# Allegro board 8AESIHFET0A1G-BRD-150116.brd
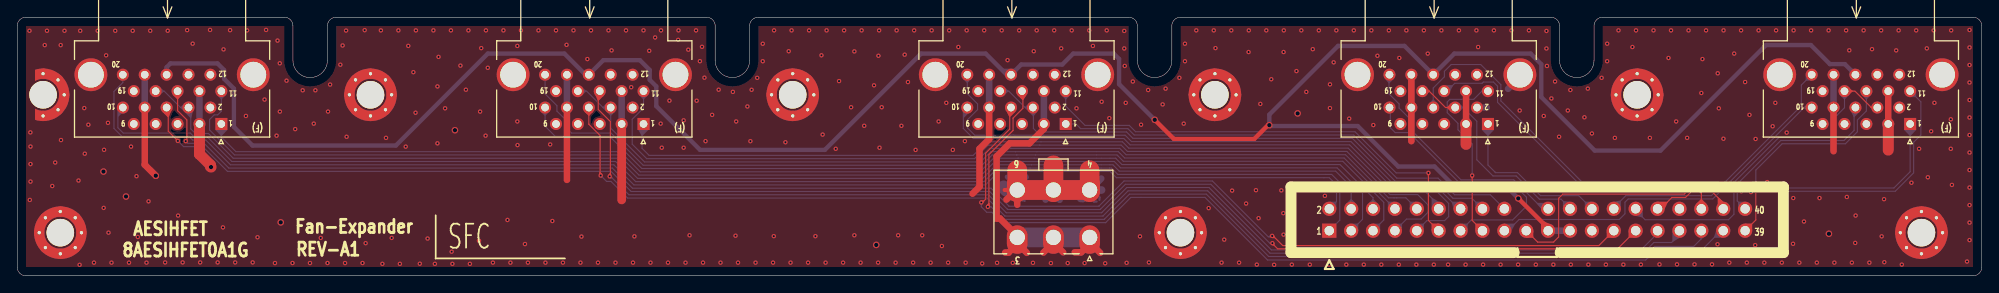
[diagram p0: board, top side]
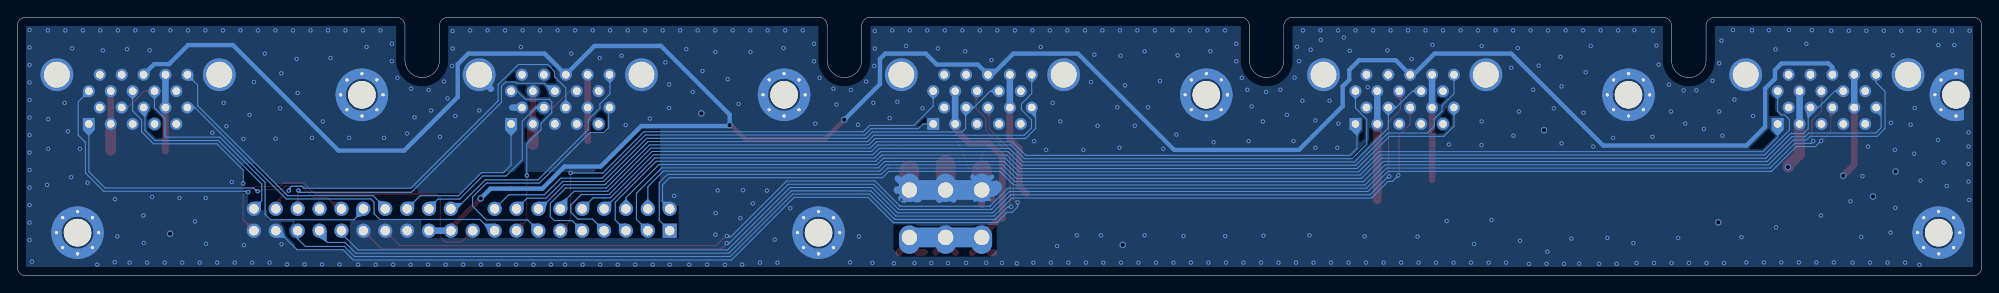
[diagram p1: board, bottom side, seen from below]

Outline 228 x 30 mm; copper layers: TOP, BOTTOM. Coordinates in mm from the lower left corner of the outline.
Outline path: 0,29 0,1 arc(0.29,0.29) 1,0 227,0 arc(227.71,0.29) 228,1 228,29 arc(227.71,29.71) 227,30 184,30 arc(183.29,29.71) 183,29 183,25 arc(181,23) 179,25 179,29 arc(178.71,29.71) 178,30 135,30 arc(134.29,29.71) 134,29 134,25 arc(132,23) 130,25 130,29 arc(129.71,29.71) 129,30 86,30 arc(85.29,29.71) 85,29 85,25 arc(83,23) 81,25 81,29 arc(80.71,29.71) 80,30 37,30 arc(36.29,29.71) 36,29 36,25 arc(34,23) 32,25 32,29 arc(31.71,29.71) 31,30 1,30 arc(0.29,29.71) 0,29

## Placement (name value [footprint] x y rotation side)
A1  3.5mm_8via  [A126_3_NO_ETCH]  3 21 180 top
A2  3.5mm_8via  [A126_DG]  41 21 0 top
A3  3.5mm_8via  [A126_DG]  90 21 0 top
A4  3.5mm_8via  [A126_DG]  139 21 0 top
A5  3.5mm_8via  [A126_DG]  188 21 0 top
A6  3.5mm_8via  [A126_DG]  5 5 0 top
A7  3.5mm_8via  [A126_DG]  135 5 0 top
A8  3.5mm_8via  [A126_DG]  221 5 0 top
JP1  JS-1150-06-A  [P2052_2X3]  124.46 4.45 180 top
JP2  M2554-2X10-G3  [P2X20_HD]  152.27 5.23 0 top
NOREF  -  []  2.54 76.45 0 top
NOREF#2  -  []  29.97 -13.08 0 top
NOREF#3  -  []  48.56 2.01 0 top
NOREF#4  -  []  0 0 0 top
NOREF#5  -  []  24.13 6.73 180 bottom
P1  SM401V-20P  [CHAMP050_20F]  8.55 23.33 180 top
P2  SM401V-20P  [CHAMP050_20F]  57.55 23.33 180 top
P3  SM401V-20P  [CHAMP050_20F]  106.55 23.33 180 top
P4  SM401V-20P  [CHAMP050_20F]  155.55 23.33 180 top
P5  SM401V-20P  [CHAMP050_20F]  204.55 23.33 180 top

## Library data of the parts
A1 = SCREW HOLE_0: Tolerance: ***; User Part Number: ***; room: SCREW
A2-A8 = SCREW HOLE_6: Tolerance: ***; User Part Number: ***; room: SCREW
JP1 = JS_1150_06_A: Tolerance: ***; User Part Number: ***
JP2 = HEADER_20X2_1: Tolerance: ***; User Part Number: ***
P1-P5 = CHAMP050_0: Tolerance: ***; User Part Number: ***

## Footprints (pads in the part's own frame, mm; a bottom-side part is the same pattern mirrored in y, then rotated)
A126_3_NO_ETCH
  round 3.2 hole 3.2 unplated: (0,0)
  round 1.194 hole 0.381: 3(-1.732,1.732) 4(-1.732,-1.732) 6(0,2.451) 7(0,-2.451) 8(-2.451,0)
A126_DG
  round 3.2 hole 3.2 unplated: (0,0)
  round 1.194 hole 0.381: 2(1.732,1.732) 3(-1.732,1.732) 4(-1.732,-1.732) 5(1.732,-1.732) 6(0,2.451) 7(0,-2.451) 8(-2.451,0) 9(2.451,0)
CHAMP050_20F
  rect 1.397x1.397 hole 0.889: 1(-15.138,5.715)
  round 1.397 hole 0.889: 2(-13.868,3.81) 3(-12.598,5.715) 4(-11.328,3.81) 5(-10.058,5.715) 6(-8.788,3.81) 7(-7.518,5.715) 8(-6.248,3.81) 9(-4.978,5.715) 10(-3.708,3.81) 11(-15.138,1.905) 12(-13.868,0) 13(-12.598,1.905) 14(-11.328,0) 15(-10.058,1.905) 16(-8.788,0) 17(-7.518,1.905) 18(-6.248,0) 19(-4.978,1.905) 20(-3.708,0)
  round 3.81 hole 2.997: 21(-18.847,0) 22(0,0)
P2X20_HD
  rect 1.651x1.651 hole 1.092: 1(0,0)
  round 1.651 hole 1.092: 2(0,2.54) 3(2.54,0) 4(2.54,2.54) 5(5.08,0) 6(5.08,2.54) 7(7.62,0) 8(7.62,2.54) 9(10.16,0) 10(10.16,2.54) 11(12.7,0) 12(12.7,2.54) 13(15.24,0) 14(15.24,2.54) 15(17.78,0) 16(17.78,2.54) 17(20.32,0) 18(20.32,2.54) 19(22.86,0) 21(25.4,0) 22(25.4,2.54) 23(27.94,0) 24(27.94,2.54) 25(30.48,0) 26(30.48,2.54) 27(33.02,0) 28(33.02,2.54) 29(35.56,0) 30(35.56,2.54) 31(38.1,0) 32(38.1,2.54) 33(40.64,0) 34(40.64,2.54) 35(43.18,0) 36(43.18,2.54) 37(45.72,0) 38(45.72,2.54) 39(48.26,0) 40(48.26,2.54)
P2052_2X3
  oval 2.413x3.302 hole 1.778: 1(0,0) 2(4.2,0) 3(8.4,0) 4(0,-5.5) 5(4.2,-5.5) 6(8.4,-5.5)

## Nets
12VIN: JP1.1 JP1.2 JP1.3 P1.3 P1.8 P1.13 P1.18 P2.3 P2.8 P2.13 P2.18 P3.3 P3.8 P3.13 P3.18 P4.3 P4.8 P4.13 P4.18 P5.3 P5.8 P5.13 P5.18
GND: A1.3 A1.4 A1.6 A1.7 A1.8 A2.2 A2.3 A2.4 A2.5 A2.6 A2.7 A2.8 A2.9 A3.2 A3.3 A3.4 A3.5 A3.6 A3.7 A3.8 A3.9 A4.2 A4.3 A4.4 A4.5 A4.6 A4.7 A4.8 A4.9 A5.2 A5.3 A5.4 A5.5 A5.6 A5.7 A5.8 A5.9 A6.2 A6.3 A6.4 A6.5 A6.6 A6.7 A6.8 A6.9 A7.2 A7.3 A7.4 A7.5 A7.6 A7.7 A7.8 A7.9 A8.2 A8.3 A8.4 A8.5 A8.6 A8.7 A8.8 A8.9 JP1.4 JP1.5 JP1.6 JP2.25 JP2.34 P1.2 P1.7 P1.9 P1.12 P1.14 P1.19 P1.21 P1.22 P2.2 P2.7 P2.9 P2.12 P2.14 P2.19 P2.21 P2.22 P3.2 P3.7 P3.9 P3.12 P3.14 P3.19 P3.21 P3.22 P4.2 P4.7 P4.9 P4.12 P4.14 P4.19 P4.21 P4.22 P5.2 P5.7 P5.9 P5.12 P5.14 P5.19 P5.21 P5.22
BIAS3V3_VCC: JP2.21 JP2.23 P1.16 P2.16 P3.16 P4.16 P5.16
FAN_DIRECTION_0: JP2.3 P1.11
FAN_DIRECTION_1: JP2.7 P2.11
FAN_DIRECTION_2: JP2.11 P3.11
FAN_DIRECTION_3: JP2.15 P4.11
FAN_DIRECTION_4: JP2.19 P5.11
FAN_PRESENT_0: JP2.1 P1.10
FAN_PRESENT_1: JP2.5 P2.10
FAN_PRESENT_2: JP2.9 P3.10
FAN_PRESENT_3: JP2.13 P4.10
FAN_PRESENT_4: JP2.17 P5.10
FAN_PWM_0: JP2.4 P1.4 P1.17
FAN_PWM_1: JP2.10 P2.4 P2.17
FAN_PWM_2: JP2.16 P3.4 P3.17
FAN_PWM_3: JP2.24 P4.4 P4.17
FAN_PWM_4: JP2.30 P5.4 P5.17
FAN_TACH_0: JP2.6 P1.1
FAN_TACH_1: JP2.2 P1.20
FAN_TACH_2: JP2.12 P2.1
FAN_TACH_3: JP2.8 P2.20
FAN_TACH_4: JP2.18 P3.1
FAN_TACH_5: JP2.14 P3.20
FAN_TACH_6: JP2.26 P4.1
FAN_TACH_7: JP2.22 P4.20
FAN_TACH_8: JP2.32 P5.1
FAN_TACH_9: JP2.28 P5.20
I2C_SCL_FAN0: JP2.29 P1.6
I2C_SCL_FAN1: JP2.33 P2.6
I2C_SCL_FAN2: JP2.37 P3.6
I2C_SCL_FAN3: JP2.38 P4.6
I2C_SCL_FAN4: JP2.40 P5.6
I2C_SDA_FAN0: JP2.27 P1.15
I2C_SDA_FAN1: JP2.31 P2.15
I2C_SDA_FAN2: JP2.35 P3.15
I2C_SDA_FAN3: JP2.36 P4.15
I2C_SDA_FAN4: JP2.39 P5.15

Pads without a net: P1 5; P2 5; P3 5; P4 5; P5 5

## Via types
v1: diameter 0.508, hole 0.254, TOP to BOTTOM, 463 vias
v2: diameter 0.762, hole 0.508, TOP to BOTTOM, 12 vias

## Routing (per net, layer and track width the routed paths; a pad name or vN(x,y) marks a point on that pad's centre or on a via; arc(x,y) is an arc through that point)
12VIN: length 133.5
  TOP w0.762: P5.3 P5.13 ; 121.39,2.72 120.26,3.84 120.26,3.85 ; 120.26,3.85 119.1,2.69 ; 120.26,3.85 JP1.2 ; 124.46,3.89 JP1.1 ; 124.46,3.89 125.68,2.67 ; 124.46,3.89 124.46,3.71 123.47,2.72 122.73,2.72 ; P1.8 14.8,12.89 v2(16.08,11.61) ; P4.3 P4.13 ; P3.8 112.8,15.85 111.68,14.73 111.68,10.34 110.87,9.53 ; 116.06,3.78 JP1.3 116.06,4.64 114.06,6.64 113.67,6.64 113.67,13.84 115.19,15.37 117.47,15.37 119.15,17.04 P3.3 ; 116.06,3.78 116.06,3.69 115.06,2.69 114.66,2.69 ; 116.06,3.78 117.17,2.67 ; 161.8,15.62 P4.8 P4.18 ; P2.8 63.8,11.13 ; P5.8 210.8,14.46
  TOP w1.016: P2.3 70.15,8.81
  TOP w1.27: P1.3 21.15,14.11 21.16,14.11 22.43,12.84 22.43,12.67 v2(22.49,12.61) ; P4.3 168.15,15.24 ; P5.3 217.15,14.58
  BOTTOM w0.762: P3.3 P3.13 ; P2.13 P2.3 ; P3.8 P3.18 ; P1.3 P1.13 ; P2.8 P2.18 ; P5.8 P5.18 ; P1.8 P1.18
  BOTTOM w2.286: JP1.1 JP1.2 JP1.3
GND: length 51.4
  TOP w0.508: 115.92,9.95 114.61,9.95
  TOP w0.762: 114.81,8.84 115.92,9.95 JP1.6 116.06,8.25
  TOP w2.286: JP1.5 JP1.4 124.46,12.24 ; JP1.5 120.26,12.81 ; JP1.5 JP1.6 116.06,12.26
  BOTTOM w0.254: 125.6,8.81 125.6,9.09 124.75,9.95 ; 116.06,9.2 JP1.6 ; 116.06,9.2 116.2,9.2 116.64,8.76 116.84,8.76 116.92,8.69 ; 116.06,9.2 115.83,9.2 115.44,8.81 115.11,8.81 ; 124.46,9.68 124.46,9.12 124.97,8.61 125.27,8.61
  BOTTOM w0.508: 116.06,10.46 JP1.6 ; 116.06,10.46 116.17,10.46 117.12,11.4 117.12,11.53 ; 116.06,10.46 115.14,11.38 114.96,11.38 114.86,11.48
  BOTTOM w0.762: 120.26,9.75 120.26,9.53 120.98,8.81 ; 120.26,9.75 JP1.5 ; 120.26,9.75 119.35,8.84 ; 173.02,21.69 174.4,23.06 P4.21 ; 124.48,9.95 125.81,11.28 ; P4.2 170.55,19.52 ; 123.39,8.91 123.7,8.91 124.46,9.68 JP1.4
  BOTTOM w0.889: 125.84,9.95 JP1.4
  BOTTOM w1.524: 114.48,10.29 114.81,9.95 JP1.6
  BOTTOM w2.286: JP1.6 JP1.5 JP1.4
  vias: v1(1.42,28.43) v1(1.52,16.64) v1(1.54,14.99) v1(1.54,12.96) v1(1.54,10.93) v1(1.46,8.8) v1(3.19,26.77) v1(3.45,28.43) v1(4.06,10.41) v1(4.41,13.14) v1(5.05,26.77) v1(5.08,15.75) v1(5.48,28.43) v1(7.11,11.05) v1(7.24,1.27) v1(7.31,28.43) v1(7.78,19.46) v1(7.84,14.16) v1(8.26,17.53) v1(8.91,1.52) v1(9.34,28.43) v1(10.03,7.87) v1(10.08,14.61) v1(10.32,25.58) v1(10.53,17.75) v1(10.59,5) v1(10.94,1.52) v1(11.37,28.43) v1(12.97,1.52) v1(13.21,14.99) v1(13.4,28.43) v1(13.84,11.56) v1(14,4.5) v1(15,1.52) v1(15.24,8.64) v1(15.43,28.43) v1(17.17,1.55) v1(17.47,28.43) v1(18.67,6.99) v1(19.2,1.55) v1(19.72,28.5) v1(20.36,26.93) v1(21.23,1.55) v1(22.38,28.53) v1(23.26,1.55) v1(23.94,26.27) v1(23.88,5.61) v1(24.7,28.5) v1(25.29,1.55) v1(26.54,18.54) v1(26.67,28.48) v1(27.33,1.55) v1(27.89,4.47) v1(28.7,20.45) v1(28.88,28.53) v1(29.91,1.48) v1(30.1,16.26) v1(30.21,27.29) v1(30.47,24.66) v1(30.48,19.05) v1(31.26,22.64) v1(31.95,1.48) v1(32.26,17.02) v1(33.13,21.52) v1(33.98,1.48) v1(34.42,17.65) v1(34.6,21.52) v1(35.23,4.39) v1(36.01,1.48) v1(36.07,19.05) v1(36.31,22.19) v1(37.5,24.49) v1(37.76,26.72) v1(38.04,1.48) v1(38.16,28.45) v1(38.23,16.13) v1(40.07,1.48) v1(40.32,28.5) v1(40.44,3.78) v1(42.2,28.48) v1(42.38,1.38) v1(42.8,16) v1(43.46,4.39) v1(44.24,28.48) v1(44.41,1.38) v1(45.09,14.99) v1(45.38,26.67) v1(45.97,23.62) v1(46.23,18.92) v1(46.27,28.48) v1(46.72,1.4) v1(47.62,4.32) v1(48.3,28.48) v1(48.47,1.38) v1(48.77,21.97) v1(48.77,15.37) v1(48.9,25.4) v1(49.66,19.43) v1(50.33,28.48) v1(50.42,2.79) v1(50.5,1.38) v1(51.44,24.38) v1(52.07,21.59) v1(52.36,28.48) v1(52.54,1.38) v1(53.59,4.06) v1(53.72,19.05) v1(53.85,26.42) v1(54.4,28.48) v1(54.36,16.26) v1(54.61,24.13) v1(55.21,1.52) v1(56.43,28.48) v1(56.9,6.48) v1(57.24,1.52) v1(58.04,26.67) v1(58.04,17.91) v1(58.06,15.16) v1(58.46,28.48) v1(58.93,3.68) v1(59.27,1.52) v1(60.49,28.48) v1(61.3,1.52) v1(61.85,15.24) v1(62.1,6.35) v1(62.52,28.48) v1(63.33,1.52) v1(63.75,26.8) v1(64.56,28.48) v1(65.37,1.52) v1(65.48,4.55) v1(66.17,25.15) v1(66.59,28.48) v1(67.4,1.52) v1(68.62,28.48) v1(68.98,26.15) v1(69.43,1.52) v1(70.65,28.48) v1(71.25,21.88) v1(71.46,1.52) v1(71.63,4.57) v1(72.68,28.48) v1(73.35,26.1) v1(73.49,1.52) v1(74.03,27.65) v1(74.72,28.48) v1(74.68,17.65) v1(74.8,14.86) v1(75.53,1.52) v1(75.69,20.32) v1(76.75,28.48) v1(76.7,27.37) v1(77.34,18.03) v1(77.34,14.86) v1(77.56,1.52) v1(77.88,26.23) v1(78.03,4.7) v1(78.78,28.48) v1(78.85,20.31) v1(79.23,24.9) v1(79.48,26.57) v1(79.59,1.52) v1(79.76,22.99) v1(79.88,15.62) v1(80.64,18.67) v1(81.41,21.59) v1(81.62,1.52) v1(83.06,21.34) v1(83.44,17.91) v1(83.36,4.65) v1(83.65,1.52) v1(84.74,19.65) v1(85.09,15.62) v1(85.23,21.58) v1(85.69,1.52) v1(85.88,22.97) v1(86.52,26.92) v1(86.52,24.89) v1(87.72,1.52) v1(87.84,28.48) v1(87.81,4.6) v1(89.15,15.49) v1(89.54,26.06) v1(89.75,1.52) v1(89.87,28.48) v1(91.78,1.52) v1(91.9,28.48) v1(92.63,4.6) v1(93.34,25.58) v1(93.47,16.38) v1(93.81,1.52) v1(93.93,28.48) v1(95,14.73) v1(95.38,22.59) v1(95.85,1.52) v1(95.96,28.48) v1(96.77,19.56) v1(97.16,26.04) v1(97.16,4.7) v1(97.88,1.52) v1(98,28.48) v1(98.3,17.4) v1(99.44,22.1) v1(99.95,25.53) v1(99.91,1.52) v1(100.03,28.48) v1(100.08,14.86) v1(100.33,19.56) v1(101.94,1.52) v1(102.06,28.48) v1(102.23,4.7) v1(102.62,17.4) v1(103,25.65) v1(103.38,22.48) v1(103.97,1.52) v1(104.09,28.48) v1(104.27,14.61) v1(105.03,4.7) v1(106.01,1.52) v1(106.12,28.48) v1(106.93,17.91) v1(107.31,3.45) v1(107.82,20.07) v1(108.04,1.52) v1(108.16,28.48) v1(108.58,14.61) v1(109.22,26.54) v1(109.98,15.62) v1(110.07,1.52) v1(110.19,28.48) v1(111.99,1.43) v1(112.22,28.48) v1(113.72,1.5) v1(114.25,28.48) v1(114.94,25.02) v1(115.54,1.5) v1(116.28,28.48) v1(117.88,1.5) v1(117.98,26.06) v1(118.32,28.48) v1(119.96,1.47) v1(120.35,28.48) v1(121.16,26.39) v1(121.92,1.47) v1(122.38,28.48) v1(122.94,19.43) v1(123.88,1.47) v1(124.41,28.48) v1(124.84,26.67) v1(125.86,20.19) v1(126.26,1.45) v1(126.44,28.48) v1(126.75,18.29) v1(128.48,28.41) v1(128.48,26.38) v1(128.54,24.35) v1(128.65,20.07) v1(128.75,1.5) v1(129.47,22.54) v1(130.3,4.57) v1(130.43,17.53) v1(131.25,21.56) v1(131.34,1.55) v1(132.93,19.88) v1(133.28,21.71) v1(134.88,22.97) v1(135.38,17.65) v1(135.52,26.92) v1(135.52,24.89) v1(136.84,28.48) v1(138.28,7.85) v1(138.87,28.48) v1(139.06,26.42) v1(139.77,1.52) v1(140.08,4.19) v1(140.9,28.48) v1(141,9.88) v1(141.8,1.52) v1(142.62,8.38) v1(142.93,28.48) v1(142.91,25.96) v1(143.76,9.93) v1(143.87,1.3) v1(144.07,6.68) v1(144.27,19.94) v1(144.96,28.48) v1(145.54,22.8) v1(145.87,1.27) v1(146.71,9.91) v1(146.94,7.26) v1(147,28.48) v1(146.97,25.96) v1(146.96,4.78) v1(147.93,1.3) v1(148.46,23.75) v1(149.03,28.48) v1(149.61,21.34) v1(150.01,1.3) v1(150.36,26.29) v1(151.06,28.48) v1(151.76,9.27) v1(152.27,1.3) v1(152.35,22.21) v1(152.35,19.46) v1(152.78,24.77) v1(153.09,28.48) v1(154.25,1.3) v1(154.58,18.24) v1(155.12,28.48) v1(156.28,1.3) v1(157.16,28.48) v1(157.39,17.49) v1(157.86,25.53) v1(158.31,1.3) v1(159.19,28.48) v1(160.35,1.3) v1(160.4,25.27) v1(161.22,28.48) v1(162.38,1.3) v1(163.25,28.48) v1(163.7,25.78) v1(164.41,1.3) v1(165.28,28.48) v1(166.06,1.3) v1(167.32,28.48) v1(168.09,1.3) v1(169.35,28.48) v1(169.54,26.54) v1(170.12,1.3) v1(171.38,28.48) v1(172.16,1.3) v1(173.41,28.48) v1(174.19,1.3) v1(174.37,19.18) v1(175.44,28.48) v1(176.25,1.3) v1(177.16,18.54) v1(177.48,28.41) v1(177.48,26.37) v1(177.54,24.34) v1(178.05,20.57) v1(178.28,1.3) v1(178.48,22.54) v1(178.94,16.13) v1(179.96,19.18) v1(180.25,21.56) v1(180.31,1.3) v1(181.89,18.39) v1(182.28,21.72) v1(182.34,1.3) v1(182.75,16.51) v1(183.88,22.97) v1(184.37,1.3) v1(184.52,26.93) v1(184.52,24.9) v1(185.42,16) v1(185.84,28.48) v1(186.41,1.3) v1(187.45,26.54) v1(187.87,28.48) v1(188.44,1.3) v1(189.48,16) v1(189.9,28.48) v1(190.6,1.32) v1(191.64,25.27) v1(191.94,28.48) v1(192.53,17.91) v1(192.63,1.32) v1(193.8,16) v1(193.97,28.48) v1(194.66,1.32) v1(195.45,21.21) v1(195.58,25.15) v1(196,28.48) v1(196.69,1.32) v1(197.33,3.66) v1(197.36,23.5) v1(197.49,19.43) v1(198.03,28.48) v1(198.02,15.9) v1(198.7,1.52) v1(199.26,25.78) v1(200.06,28.48) v1(200.53,22.48) v1(200.73,1.52) v1(201.04,18.67) v1(201.7,3.56) v1(201.75,15.88) v1(202.1,28.48) v1(202.76,1.52) v1(203.1,10.87) v1(203.73,17.35) v1(204.04,20.07) v1(204.13,28.48) v1(204.8,1.52) v1(205.36,16.61) v1(206.12,9.02) v1(206.1,3.71) v1(206.16,28.48) v1(206.83,1.52) v1(207.37,6.3) v1(208.19,28.48) v1(208.86,1.52) v1(209.17,9.02) v1(210.22,28.48) v1(210.89,1.52) v1(212.26,28.48) v1(212.34,9.14) v1(212.62,26.16) v1(212.92,1.52) v1(213.31,3.81) v1(213.36,6.99) v1(214.29,28.48) v1(214.96,1.52) v1(215.26,26.29) v1(216.32,28.48) v1(216.38,4.57) v1(216.66,8.89) v1(216.69,1.57) v1(218.06,26.15) v1(218.35,28.48) v1(218.72,1.3) v1(219.84,10.79) v1(220.38,28.48) v1(220.73,14.73) v1(221.63,26.39) v1(221.74,11.43) v1(222.12,16.76) v1(222.42,28.48) v1(222.5,20.07) v1(224.45,28.48) v1(224.41,18.16) v1(224.41,14.73) v1(224.54,10.54) v1(226.29,1.65) v1(226.58,28.52) v1(226.58,26.49) v1(226.58,24.46) v1(226.58,22.43) v1(226.58,20.4) v1(226.58,18.36) v1(226.58,16.33) v1(226.58,14.3) v1(226.58,12.27) v1(226.58,10.24) v1(226.58,8.2) v1(226.58,6.17) v1(226.58,4.14) v2(10.01,12.09) v2(12.62,9.19) v2(30.58,6.2) v2(50.8,16.89) v2(99.69,3.58) v2(148.6,18.84) v2(210.26,4.88)
BIAS3V3_VCC: length 290.3
  TOP w0.508: v2(145.31,17.48) 145.16,17.48 143.56,15.88 134.24,15.88 v2(132.02,18.1) ; v2(174.21,8.98) 174.33,8.85 177.67,5.51 JP2.21
  BOTTOM w0.508: P5.16 212.11,24.56 210.37,24.56 208.16,26.77 202.96,26.77 190.72,14.53 183.08,14.53 176.88,20.73 176.88,24.54 175.64,25.78 166.79,25.78 P4.16 161,26.67 153.29,26.67 145.31,18.69 v2(145.31,17.48) 145.41,17.37 155.57,17.37 160.27,12.67 164.49,12.67 167.06,10.11 170.69,10.11 173.07,10.11 v2(174.21,8.98) ; 66.4,23.4 65.89,23.4 63.5,25.78 54.61,25.78 43.94,15.11 27.3,15.11 25.15,17.27 25.15,21.72 24,22.86 24,23.88 23.24,24.64 17.78,24.64 17.34,24.2 P1.16 ; 66.4,23.4 68.03,25.02 72.26,25.02 73.41,23.88 73.41,22.73 74.17,21.97 74.17,19.68 79.25,14.61 93.73,14.61 104.9,25.78 112.39,25.78 114.85,23.33 P3.16 116.52,24.51 121.28,24.51 122.56,25.78 127.25,25.78 127.88,25.16 127.88,22.24 v2(132.02,18.1) ; 66.4,23.4 P2.16
  BOTTOM w0.762: JP2.23 JP2.21
FAN_DIRECTION_0: length 148.4
  BOTTOM w0.127: P1.11 23.69,19.09 23.27,18.67 22.86,18.67 22.33,18.14 22.33,16.92 25.22,14.02 69.82,14.02 72.15,11.68 111.9,11.68 113.47,13.26 116.32,13.26 116.32,13.26 117.87,13.26 117.87,13.26 125.28,13.26 125.81,13.26 126.82,13.26 127.32,13.26 128.06,12.52 153.19,12.52 156.13,9.58 156.13,6.55 JP2.3
FAN_DIRECTION_1: length 108.9
  BOTTOM w0.127: JP2.7 161.24,6.58 162.94,6.58 163.75,7.39 163.75,8.2 162.53,9.42 159.95,9.42 159.63,9.42 159.63,9.42 159.32,9.42 154.31,14.43 128.85,14.43 128.11,15.16 118.66,15.16 115.33,15.16 115.32,15.16 114.09,15.16 114.09,15.16 112.68,15.16 111.11,13.59 73.05,13.59 71.37,15.27 71.37,18.16 72.69,19.48 P2.11
FAN_DIRECTION_2: length 54.2
  TOP w0.127: JP2.11 163.78,6.42 v1(163.78,11.94)
  BOTTOM w0.127: P3.11 121.69,19.69 123.93,17.45 129.06,17.45 129.8,16.71 155.26,16.71 160.04,11.94 v1(163.78,11.94)
FAN_DIRECTION_3: length 21.9
  TOP w0.127: v1(168.86,11.63) 168.86,6.42 JP2.15
  BOTTOM w0.127: v1(168.86,11.63) 168.86,15.29 167.21,16.94 167.21,17.68 165.96,18.92 165.96,20.17 166.27,20.47 169.04,20.47 169.99,21.42 P4.11
FAN_DIRECTION_4: length 62.7
  TOP w0.127: v1(201.21,9.72) 201.16,9.72 200.51,10.36 197.46,10.36 197.05,10.77 194.76,10.77 193.47,9.47 179.37,9.47 178.89,8.99 178.89,4.5 178.31,3.91 176.45,3.91 JP2.19
  BOTTOM w0.127: v1(201.21,9.72) 201.29,9.8 217.96,9.8 220.09,11.94 220.09,15.49 220.93,16.33 220.93,20.18 P5.11
FAN_PRESENT_0: length 154.6
  BOTTOM w0.127: JP2.1 153.49,6.45 153.49,10.82 152.55,11.76 151.81,11.76 127.73,11.76 127,12.5 126.78,12.5 126.78,12.5 125.81,12.5 125.28,12.5 117.55,12.5 117.55,12.5 116.63,12.5 116.63,12.5 113.79,12.5 112.21,10.92 71.78,10.92 69.44,13.26 24.91,13.26 22.04,16.13 20.52,16.13 20.09,16.56 12.3,16.56 11.68,17.18 11.68,19.27 11.94,19.52 P1.10
FAN_PRESENT_1: length 108.3
  BOTTOM w0.127: P2.10 61.26,17.35 62.43,16.18 68.75,16.18 72.49,12.45 111.58,12.45 113.15,14.02 116,14.02 116,14.02 118.19,14.02 118.19,14.02 125.28,14.02 127.64,14.02 127.72,13.94 127.81,13.85 128.37,13.28 153.84,13.28 158.6,8.53 158.6,6.47 JP2.5
FAN_PRESENT_2: length 68.4
  BOTTOM w0.127: P3.10 109.8,19.07 109.8,17.09 110.97,15.93 113.75,15.93 118.98,15.93 128.43,15.93 129.16,15.19 154.63,15.19 159.63,10.19 164.34,10.19 166.13,8.4 166.13,6.87 165.66,6.4 163.6,6.4 JP2.9
FAN_PRESENT_3: length 31.4
  BOTTOM w0.127: JP2.13 168.76,6.48 173.56,6.48 175.16,8.08 175.16,9.12 173.52,10.75 167.4,10.75 161.54,16.61 159.92,16.61 159.36,17.17 159.36,19.42 P4.10
FAN_PRESENT_4: length 42.4
  BOTTOM w0.127: JP2.17 173,5.23 174.29,6.53 185.93,6.53 186.59,7.19 186.59,8.53 186.97,8.92 196.78,8.92 207.38,19.52 P5.10
FAN_PWM_0: length 148.5
  BOTTOM w0.127: JP2.4 154.81,10.34 153.01,12.14 127.9,12.14 127.16,12.88 126.81,12.88 125.81,12.88 125.28,12.88 117.71,12.88 116.48,12.88 113.63,12.88 112.05,11.3 71.99,11.3 69.66,13.64 25.06,13.64 22.19,16.51 20.68,16.51 20.14,17.04 20.14,19.26 P1.4 18.96,19.52 17.06,21.42 P1.17
FAN_PWM_1: length 105.7
  BOTTOM w0.127: P2.17 66.08,21.42 67.98,19.52 P2.4 68.88,17.13 72.8,13.21 111.26,13.21 112.84,14.78 115.33,14.78 115.34,14.78 118.5,14.78 118.5,14.78 127.95,14.78 128.69,14.05 154.16,14.05 159.16,9.04 159.79,9.04 160.11,9.04 161.16,9.04 JP2.10
FAN_PWM_2: length 63
  BOTTOM w0.127: P3.17 115.07,21.42 116.98,19.52 P3.4 117.93,19.47 117.93,17.09 118.34,16.69 119.29,16.69 128.74,16.69 129.48,15.95 154.95,15.95 159.95,10.95 164.67,10.95 166.63,8.99 168.83,8.99 JP2.16
FAN_PWM_3: length 25.5
  TOP w0.127: P4.4 165.77,19.52 163.87,21.42 P4.17
  BOTTOM w0.127: JP2.24 180.21,7.85 179.17,8.89 176.66,8.89 173.96,11.58 171.27,11.58 169.39,13.46 169.39,17.93 167.81,19.52 P4.4
FAN_PWM_4: length 40.2
  TOP w0.127: P5.4 215.18,19.52 213.27,21.42 212.94,21.42 P5.17
  BOTTOM w0.127: JP2.30 187.83,7.59 188.93,6.5 198.6,6.5 199.24,7.14 199.24,10.83 204.48,16.08 210.74,16.08 210.87,16.21 210.87,18.31 211.16,18.61 211.18,18.61 212.07,19.5 P5.17
FAN_TACH_0: length 140.7
  BOTTOM w0.127: P1.1 23.69,16.09 25.38,14.4 69.97,14.4 72.31,12.06 111.74,12.06 113.31,13.64 116.16,13.64 118.03,13.64 125.28,13.64 125.81,13.64 126.82,13.64 127.48,13.64 127.48,13.64 127.54,13.58 128.22,12.9 153.52,12.9 157.35,9.07 JP2.6
FAN_TACH_1: length 155.7
  BOTTOM w0.127: JP2.2 153.11,8.61 153.11,10.54 152.27,11.38 151.66,11.38 151.66,11.38 127.57,11.38 126.84,12.11 126.62,12.11 126.62,12.12 126.05,12.12 125.73,12.12 125.28,12.12 116.79,12.12 116.79,12.12 113.94,12.12 112.37,10.54 71.58,10.54 69.24,12.88 24.75,12.88 21.88,15.75 20.36,15.75 19.93,16.18 12.14,16.18 11.23,17.09 11.23,21.39 12.26,22.42 P1.20
FAN_TACH_2: length 99.8
  BOTTOM w0.127: P2.1 72.52,17.44 72.52,14.78 73.33,13.97 110.95,13.97 112.52,15.54 113.93,15.54 113.94,15.55 118.82,15.55 118.82,15.54 128.27,15.54 129.01,14.81 154.47,14.81 159.48,9.8 159.79,9.8 163.37,9.8 164.97,8.2 JP2.12
FAN_TACH_3: length 108.5
  BOTTOM w0.127: P2.20 61.26,21.11 62.64,19.74 62.64,19.1 63.55,18.19 63.55,17.35 64.34,16.56 68.91,16.56 72.64,12.83 111.42,12.83 113,14.4 115.84,14.4 118.34,14.4 125.28,14.4 127.8,14.4 128.01,14.18 128.53,13.67 154,13.67 JP2.8
FAN_TACH_4: length 55
  BOTTOM w0.127: P3.1 122.87,17.61 123.42,17.07 128.9,17.07 129.64,16.33 155.1,16.33 160.11,11.33 164.9,11.33 166.83,9.4 170.97,9.4 JP2.18
FAN_TACH_5: length 68.3
  BOTTOM w0.127: P3.20 110.26,21.14 111.46,19.94 111.46,19.28 110.29,18.11 110.29,17.15 111.13,16.31 112.92,16.31 112.99,16.31 112.99,16.31 113.45,16.31 113.45,16.31 115.28,16.31 115.6,16.33 115.78,16.31 119.13,16.31 119.13,16.31 128.59,16.31 129.32,15.57 154.79,15.57 159.79,10.57 164.52,10.57 167.31,7.77 JP2.14
FAN_TACH_6: length 18.9
  BOTTOM w0.127: P4.1 170.69,12.85 171.48,12.06 171.58,11.96 174.12,11.96 176.79,9.3 181.23,9.3 JP2.26
FAN_TACH_7: length 27.2
  BOTTOM w0.127: JP2.22 177.05,7.77 173.68,11.13 167.56,11.13 161.72,16.97 161.72,18.11 160.38,19.46 160.38,19.94 159.21,21.11 159.21,23.28 P4.20
FAN_TACH_8: length 37.1
  TOP w0.127: v1(200.1,9.8) 199.92,9.98 197.3,9.98 196.9,10.39 194.92,10.39 193.62,9.09 192.05,9.09 190.73,7.77 JP2.32
  BOTTOM w0.127: v1(200.1,9.8) 200.2,9.8 200.58,10.19 217.8,10.19 219.69,12.07 P5.1
FAN_TACH_9: length 30.9
  BOTTOM w0.127: P5.20 207.06,22.13 207.06,19.74 196.62,9.3 186.69,9.3 185.29,7.9 JP2.28
I2C_SCL_FAN0: length 182.1
  TOP w0.127: P1.6 17.53,19.33 17.53,16.76 v1(18.64,15.65) ; JP2.29 185.73,3.12 146.28,3.12 145.67,3.73 v1(145.67,3.78)
  BOTTOM w0.127: v1(18.64,15.65) 19.3,14.99 21.53,14.99 24.4,12.12 68.91,12.12 71.25,9.78 112.23,9.78 112.23,9.78 112.86,9.78 114.91,7.73 114.95,7.69 125.68,7.69 125.72,7.73 125.72,7.73 128.61,10.62 138.53,10.62 145.36,3.78 v1(145.67,3.78)
I2C_SCL_FAN1: length 141.2
  TOP w0.127: v1(67.72,11.63) 67.64,11.71 67.64,16.29 66.34,17.59 P2.6
  BOTTOM w0.127: JP2.33 192.91,4.78 192,3.86 189.95,3.86 188.7,2.62 145.4,2.62 138.16,9.86 128.93,9.86 126.04,6.97 126.04,6.97 126,6.93 114.64,6.93 114.6,6.97 112.55,9.02 70.84,9.02 68.9,10.95 68.4,10.95 v1(67.72,11.63)
I2C_SCL_FAN2: length 105.5
  TOP w0.127: P3.6 115.19,19.37 115.19,17.02 112.39,14.22 112.39,8.89 112.01,8.51 v1(111.89,8.51)
  BOTTOM w0.127: v1(111.89,8.51) 111.89,8 112.52,7.37 113.12,7.37 114.31,6.17 114.32,6.16 126.31,6.16 126.32,6.17 129.24,9.09 130.43,9.09 130.43,9.09 137.84,9.09 145.11,1.83 188.99,1.83 190.19,3.02 195.53,3.02 197.74,5.23 JP2.37
I2C_SCL_FAN3: length 46.2
  TOP w0.127: JP2.38 197.99,8.46 196.57,9.88 v1(196.49,9.88)
  BOTTOM w0.127: v1(196.49,9.88) 196.49,10.06 196.16,10.39 195,10.39 194.77,10.16 182.32,10.16 172.19,20.29 172.19,22.17 169.85,24.51 166.42,24.51 165.63,23.72 165.63,23.09 164.34,21.79 P4.6
I2C_SCL_FAN4: length 22.1
  BOTTOM w0.127: JP2.40 199.62,8.68 199.62,10.64 204.67,15.7 212.01,15.7 213.18,16.87 213.18,19.36 P5.6
I2C_SDA_FAN0: length 180.3
  TOP w0.127: JP2.27 183.57,3.51 146.86,3.51 145.75,4.62 v1(145.64,4.62) ; P1.15 18.61,19.16 19.68,18.08 19.68,15.75 v1(19.56,15.62)
  BOTTOM w0.127: v1(145.64,4.62) 145.54,4.52 145.19,4.52 138.71,11 128.45,11 125.57,8.11 125.56,8.11 125.52,8.07 115.11,8.07 115.07,8.11 113.02,10.16 112.07,10.16 71.41,10.16 69.07,12.5 24.56,12.5 21.69,15.37 19.81,15.37 v1(19.56,15.62)
I2C_SDA_FAN1: length 139.3
  TOP w0.127: P2.15 67.44,21.25 67.44,19.3 68.83,17.91 68.83,11.61 v1(68.76,11.53)
  BOTTOM w0.127: JP2.31 190.37,4.93 188.44,3 145.56,3 138.32,10.24 128.77,10.24 125.88,7.35 125.88,7.35 125.84,7.31 114.79,7.31 114.75,7.35 112.7,9.4 112.39,9.4 70.99,9.4 68.86,11.53 v1(68.76,11.53)
I2C_SDA_FAN2: length 104.6
  TOP w0.127: v1(112.65,8) 112.78,8.13 112.78,14.07 115.57,16.86 115.57,18.29 116.71,19.43 116.71,21.32 P3.15
  BOTTOM w0.127: JP2.35 195.45,4.29 194.56,3.4 190.03,3.4 188.86,2.24 145.24,2.24 138,9.47 129.09,9.47 126.2,6.59 126.2,6.59 126.16,6.55 114.48,6.55 114.44,6.59 113.02,8 v1(112.65,8)
I2C_SDA_FAN3: length 38.9
  TOP w0.127: JP2.36 195.45,9.83 v1(195.38,9.91)
  BOTTOM w0.127: P4.15 165.93,21.42 166.84,22.34 170.01,22.34 170.15,22.48 171.32,22.48 171.81,22 171.81,20.12 182.25,9.68 195.2,9.68 195.38,9.86 v1(195.38,9.91)
I2C_SDA_FAN4: length 26.3
  TOP w0.127: v1(201.78,10.69) 201.78,6.47 JP2.39
  BOTTOM w0.127: P5.15 214.61,19.12 213.56,18.08 213.56,16.71 212.17,15.32 204.83,15.32 201.78,12.26 v1(201.78,10.69)

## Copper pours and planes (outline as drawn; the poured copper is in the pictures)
12VIN on TOP: 14.35,14.99 14.35,12.57 19.56,7.37 62.48,7.37 64.26,5.59 106.3,5.59 109.6,2.29 128.24,2.29 129.41,3.45 129.41,6.71 132.88,10.67 160.91,10.67 162.94,12.7 169.54,12.7 170.94,11.3 218.19,11.3 218.95,12.06 218.95,14.61 218.31,15.24 176.15,15.24 175.13,16.26 144.91,16.26 144.02,15.37 128.27,15.37 126.19,13.28 126.19,8.97 124.56,7.34 112.17,7.34 111.25,8.26 111.25,10.62 66.73,10.62 65.15,12.19 24.64,12.19 21.84,14.99
GND on TOP (solid shape): outline of 222 points within 1.95,1.95 8.05,8.05
GND on TOP (solid shape): outline of 222 points within 37.95,17.95 44.05,24.05
GND on TOP (solid shape): outline of 222 points within 86.95,17.95 93.05,24.05
GND on TOP (solid shape): outline of 222 points within 131.95,1.95 138.05,8.05
GND on TOP (solid shape): outline of 222 points within 135.95,17.95 142.05,24.05
GND on TOP (solid shape): outline of 222 points within 184.95,17.95 191.05,24.05
GND on TOP (solid shape): outline of 222 points within 217.95,1.95 224.05,8.05
GND on BOTTOM (solid shape): outline of 222 points within 1.95,1.95 8.05,8.05
GND on BOTTOM (solid shape): outline of 222 points within 37.95,17.95 44.05,24.05
GND on BOTTOM (solid shape): outline of 222 points within 86.95,17.95 93.05,24.05
GND on BOTTOM (solid shape): outline of 222 points within 131.95,1.95 138.05,8.05
GND on BOTTOM (solid shape): outline of 222 points within 135.95,17.95 142.05,24.05
GND on BOTTOM (solid shape): outline of 222 points within 184.95,17.95 191.05,24.05
GND on BOTTOM (solid shape): outline of 222 points within 217.95,1.95 224.05,8.05
GND on TOP: 226.98,28.98 226.98,1.02 1.02,1.02 1.02,28.98 30.98,28.98 30.98,25 34,21.98 37.02,25 37.02,28.98 79.98,28.98 79.98,25 83,21.98 86.02,25 86.02,28.98 128.98,28.98 128.98,25 132,21.98 135.02,25 135.02,28.98 177.98,28.98 177.98,25 181,21.98 184.02,25 184.02,28.98 ; 5 cut-outs
GND on BOTTOM: 226.98,28.98 226.98,1.02 1.02,1.02 1.02,28.98 30.98,28.98 30.98,25 34,21.98 37.02,25 37.02,28.98 79.98,28.98 79.98,25 83,21.98 86.02,25 86.02,28.98 128.98,28.98 128.98,25 132,21.98 135.02,25 135.02,28.98 177.98,28.98 177.98,25 181,21.98 184.02,25 184.02,28.98 ; 19 cut-outs

Small or netless copper shapes (teardrops, artwork), in the pictures only: 35 on TOP, 76 on BOTTOM

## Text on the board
Ref Des/Silkscreen Top: 8AESIHFET0A1G
User.18: FIGURE | SIZE | 10.0 | 15.0 | 20.0 | 35.0 | 43.0 | 70.0 | 118.0 | 126.0 | DRILL CHART: TOP to BOTTOM | ALL UNITS ARE IN MILS | TOLERANCE | +3.0/-3.0 | +2.0/-2.0 | PLATED | NON-PLATED | QTY | 463 | 61 | 12 | 100 | 39 | 6 | 10 | 8
